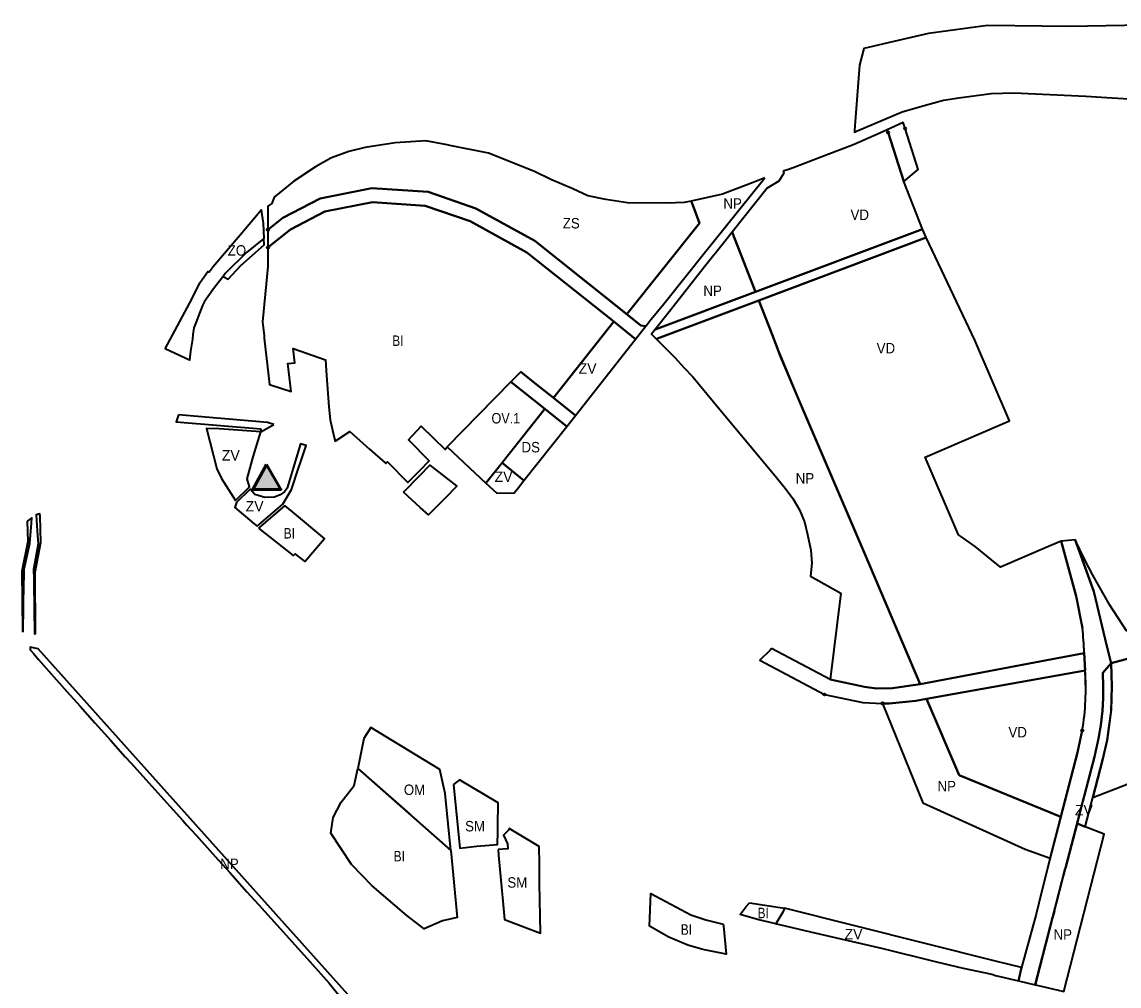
# Model space of a CAD drawing. Extents: x -650276 to -642489, y -1074311 to -1066658.
# Drawn here: x -650276 to -649019, y -1070272 to -1069167 of the extents above; entities that cross this region are included whole.
import ezdxf

# ---------------------------------------------------------------- set-up
doc = ezdxf.new("R2010")
doc.units = 0
doc.header["$LTSCALE"] = 4.8
doc.header["$PDMODE"] = 32
doc.header["$PDSIZE"] = 2.4
for name, color, linetype, lineweight in [('11', 7, 'Continuous', 35), ('12', 7, 'Continuous', 35), ('13', 7, 'Continuous', 35), ('15', 7, 'Continuous', 35), ('18', 7, 'Continuous', 35), ('2', 7, 'Continuous', 35), ('24', 7, 'Continuous', 35), ('35', 7, 'Continuous', 35), ('40', 7, 'Continuous', 35), ('41', 7, 'Continuous', 35), ('42', 7, 'Continuous', 35), ('48', 7, 'Continuous', 35), ('55', 7, 'Continuous', 53)]:
    doc.layers.add(name, color=color, linetype=linetype, lineweight=lineweight)
doc.layers.add('62', color=7, linetype='Continuous')

msp = doc.modelspace()

# ---------------------------------------------------------------- hatches: boundary and pattern name
at = {"layer": '55'}
msp.add_hatch(color=256, dxfattribs=at).paths.add_polyline_path([(-649995.793, -1069674.354), (-650011.744, -1069703), (-649979.36, -1069703)])

# ---------------------------------------------------------------- linework, layer by layer
at = {"layer": '11'}
msp.add_lwpolyline([(-649788.91, -1069654.4), (-649744.517, -1069695.746), (-649677.124, -1069610.681), (-649715.908, -1069579.804)], close=True, dxfattribs=at)
at = {"layer": '12'}
msp.add_lwpolyline([(-649891.21, -1070022.68), (-649832.007, -1070074.751), (-649784.87, -1070116.76), (-649791.31, -1070051.51), (-649797.45, -1070023.77), (-649876.31, -1069975.93), (-649884.59, -1069988.57)], close=True, dxfattribs=at)
at = {"layer": '13'}
msp.add_lwpolyline([(-648800.85, -1069841.52), (-649028.017, -1069902.109), (-649027.135, -1069928.902), (-649027.953, -1069955.702), (-649032.644, -1069990.371), (-649037.411, -1070011.659), (-649048.918, -1070055.852), (-648931.057, -1070010.171)], dxfattribs=at)
at = {"layer": '15'}
msp.add_line((-649057.868, -1069910.51), (-649058.82, -1069890.548), dxfattribs=at)
for points in [[(-649561.17, -1069515.83), (-649566.951, -1069515.099), (-649688.625, -1069418.156), (-649755.971, -1069381.179), (-649810.846, -1069362.154), (-649875.434, -1069357.751), (-649934.363, -1069369.537), (-649945.397, -1069375.277), (-649977.239, -1069391.714), (-649994.329, -1069405.451)], [(-649994.293, -1069425.949), (-649968.465, -1069405.189), (-649929.015, -1069384.784), (-649874.391, -1069373.859)], [(-649874.391, -1069373.859), (-649814.067, -1069377.972), (-649762.488, -1069395.854), (-649697.525, -1069431.522), (-649598.004, -1069510.814), (-649572.972, -1069530.758)], [(-649994.329, -1069405.451), (-649994.329, -1069405.451), (-649994.293, -1069425.949), (-649994.293, -1069425.949)], [(-649431.761, -1069486.57), (-649240.202, -1069414.528), (-649244.08, -1069404.753), (-649435.578, -1069476.772), (-649550.53, -1069519.68)], [(-649548.881, -1069530.963), (-649547.733, -1069530.185), (-649431.761, -1069486.57)], [(-649572.972, -1069530.758), (-649561.91, -1069516.78), (-649561.17, -1069515.83)], [(-649550.53, -1069519.68), (-649554.83, -1069525), (-649551.32, -1069528.49), (-649549.69, -1069530.14), (-649548.881, -1069530.963)], [(-650096.627, -1069617.746), (-650099.55, -1069625.53), (-650002.39, -1069633.65)], [(-649987.49, -1069628.6), (-649994.913, -1069626.246), (-650096.627, -1069617.746)], [(-650002.39, -1069633.65), (-650002.65, -1069637.14), (-649987.49, -1069628.6)], [(-649029.61, -1069835.47), (-649049.22, -1069801.23), (-649058.34, -1069783.72), (-649069.4, -1069760.67)], [(-649069.4, -1069760.67), (-649048, -1069820), (-649032.928, -1069882.782)], [(-649032.928, -1069882.782), (-649028.017, -1069902.109), (-648800.85, -1069841.52), (-648806.946, -1069821.79), (-648846.939, -1069832.584), (-648846.94, -1069832.584)], [(-648846.94, -1069832.584), (-648916.03, -1069847.12), (-649010.55, -1069865.09), (-649029.61, -1069835.47)], [(-649417.234, -1069885.193), (-649418.94, -1069887.36), (-649430.515, -1069898.514), (-649356.458, -1069937.945)], [(-649246.81, -1069926.27), (-649278.492, -1069930.573), (-649296.851, -1069931.092), (-649310.738, -1069929.342), (-649350.222, -1069920.873), (-649417.234, -1069885.193)], [(-649058.82, -1069890.548), (-649101.89, -1069898.73), (-649246.81, -1069926.27)], [(-649289.95, -1069948.146), (-649282.437, -1069948.342), (-649251.805, -1069945.276), (-649239.635, -1069943.094), (-649057.868, -1069910.51)], [(-649356.458, -1069937.945), (-649312.646, -1069947.342), (-649289.95, -1069948.146)]]:
    msp.add_lwpolyline(points, dxfattribs=at)
for points in [[(-650025.31, -1069446.49), (-649998.512, -1069422.926), (-649999.01, -1069415.628), (-650018.873, -1069431.749), (-650043.521, -1069455.69), (-650045.72, -1069459.1), (-650040.012, -1069461.999)], [(-649677.124, -1069610.681), (-649651.846, -1069630.82), (-649641.978, -1069618.226), (-649667.188, -1069598.14), (-649688.446, -1069581.203), (-649704.646, -1069568.296), (-649715.908, -1069579.804)]]:
    msp.add_lwpolyline(points, close=True, dxfattribs=at)
for p in [(-649994.329, -1069405.451), (-649994.293, -1069425.949), (-649356.458, -1069937.945), (-649289.95, -1069948.146)]:
    msp.add_point(p, dxfattribs=at)
at = {"layer": '18'}
for points in [[(-649781.53, -1070041.2), (-649774.45, -1070113.92), (-649754.82, -1070111.89), (-649731.12, -1070109.96), (-649730.96, -1070094.91), (-649730.89, -1070088.96), (-649730.6, -1070061.98), (-649774.73, -1070035.58)], [(-649730.57, -1070115.76), (-649730, -1070122.01), (-649726.22, -1070162.75), (-649725.49, -1070170.64), (-649723.17, -1070195.81), (-649682.04, -1070211.58), (-649683.12, -1070154.14), (-649682.98, -1070132.1), (-649683.57, -1070112.05), (-649717.72, -1070091.61), (-649718.71, -1070093.35), (-649724.36, -1070099.03), (-649719.69, -1070108.94), (-649719.24, -1070114.87)]]:
    msp.add_lwpolyline(points, close=True, dxfattribs=at)
at = {"layer": '2'}
for points in [[(-649715.908, -1069579.804), (-649704.646, -1069568.296), (-649688.446, -1069581.203), (-649667.188, -1069598.14), (-649598.004, -1069510.814), (-649697.525, -1069431.522), (-649762.488, -1069395.854), (-649814.067, -1069377.972), (-649874.391, -1069373.859), (-649929.015, -1069384.784), (-649968.465, -1069405.189), (-649994.293, -1069425.949), (-649994.53, -1069447.61), (-650000.59, -1069511.15), (-649998.81, -1069527.07), (-649998.5, -1069529.88), (-649992.59, -1069582.88), (-649967.81, -1069590.74), (-649971.38, -1069558.79), (-649963.43, -1069557.91), (-649965.26, -1069541.51), (-649928.48, -1069554.57), (-649927.3, -1069572.44)], [(-649927.3, -1069572.44), (-649924.62, -1069608.53), (-649923.17, -1069623.14), (-649918.35, -1069643.45), (-649917.38, -1069647.56), (-649900.64, -1069636.78), (-649877.82, -1069656.83), (-649859.96, -1069672.53), (-649859.17, -1069673.22), (-649857.49, -1069671.46), (-649833.94, -1069695.24), (-649833.94, -1069695.24), (-649819.98, -1069680.92), (-649809.47, -1069670.13), (-649833.38, -1069646.08), (-649818.71, -1069630.64), (-649791.3, -1069657.21), (-649788.91, -1069654.4), (-649715.908, -1069579.804)]]:
    msp.add_lwpolyline(points, dxfattribs=at)
for points in [[(-649838.99, -1069706.15), (-649820.64, -1069687.33), (-649808.96, -1069675.34), (-649777.94, -1069699.2), (-649792.13, -1069713.65), (-649807.66, -1069729.46), (-649810.41, -1069732.28), (-649819.9, -1069723.61)], [(-650004.59, -1069747.27), (-649974.86, -1069721.96), (-649966.52, -1069728.87), (-649929.38, -1069759.65), (-649951.56, -1069785.42), (-649963, -1069776.7), (-649965, -1069778.7)], [(-649922.3, -1070096.9), (-649919.55, -1070079.01), (-649910.34, -1070061.29), (-649895.45, -1070042.15), (-649891.21, -1070022.68), (-649784.87, -1070116.76), (-649777.29, -1070193.57), (-649794.37, -1070197.2), (-649815.33, -1070206.63), (-649835.28, -1070191.27), (-649874.94, -1070157.19), (-649898.55, -1070132.9)], [(-649557.21, -1070203.53), (-649555.44, -1070165.91), (-649532.57, -1070178.08), (-649509.72, -1070190.24), (-649492.67, -1070196.34), (-649472.6, -1070201.15), (-649472.43, -1070202.9), (-649469.176, -1070235.365), (-649496, -1070230), (-649513, -1070225), (-649535, -1070216)], [(-649442.63, -1070176.69), (-649402.29, -1070182.92), (-649404.2, -1070187.43), (-649412.2, -1070200.71), (-649433.3, -1070195.89), (-649453.27, -1070190.02), (-649446.19, -1070180.76)]]:
    msp.add_lwpolyline(points, close=True, dxfattribs=at)
at = {"layer": '24'}
for p, q in [((-649283.702, -1069294.132), (-649265.774, -1069350.068)), ((-649058.858, -1069889.759), (-649057.868, -1069910.51)), ((-649057.134, -1069932.873), (-649057.868, -1069910.51))]:
    msp.add_line(p, q, dxfattribs=at)
for points in [[(-648781.015, -1069167.44), (-649076.02, -1069172.683), (-649169.781, -1069171.432), (-649237.512, -1069180.731), (-649277.021, -1069189.913), (-649306.455, -1069196.754), (-649311.633, -1069197.958), (-649316.47, -1069216.91), (-649321.32, -1069281.47), (-649322.09, -1069291.73), (-649322.22, -1069293.54), (-649319.72, -1069292.47), (-649267.5, -1069270.41), (-649242.5, -1069263.3), (-649220.18, -1069257.03), (-649202.63, -1069254.4), (-649165.62, -1069249.43), (-649139.63, -1069248.73), (-649056.95, -1069252.55), (-649026.955, -1069254.366), (-649001.3, -1069255.92)], [(-649264.156, -1069289.589), (-649266.331, -1069282.804), (-649284.695, -1069291.033), (-649283.702, -1069294.132)], [(-649265.774, -1069350.068), (-649249.069, -1069336.66), (-649264.156, -1069289.589)], [(-649061.138, -1069979.243), (-649061.138, -1069979.243), (-649061.139, -1069979.254), (-649066.487, -1070004.267), (-649098.65, -1070127.795), (-649110.925, -1070177.113), (-649114.174, -1070189.816), (-649130.712, -1070250.935), (-649134.294, -1070266.095), (-649115.159, -1070270.568), (-649095.152, -1070193.731), (-649093.095, -1070186.132), (-649095.152, -1070193.731), (-649080.924, -1070137.409), (-649080.38, -1070136.996), (-649047.131, -1070009.304), (-649042.468, -1069988.477), (-649042.468, -1069988.477), (-649039.966, -1069973.035), (-649037.98, -1069956.626), (-649037.322, -1069942.129), (-649037.137, -1069928.996), (-649037.665, -1069912.977), (-649028.017, -1069902.109), (-649032.928, -1069882.782), (-649048, -1069820), (-649069.4, -1069760.67), (-649085.41, -1069762.44), (-649068, -1069825.147), (-649060.897, -1069861.994)]]:
    msp.add_lwpolyline(points, dxfattribs=at)
msp.add_lwpolyline([(-649701.211, -1069692.826), (-649651.773, -1069630.879), (-649677.124, -1069610.681), (-649726.033, -1069672.415)], close=True, dxfattribs=at)
for centre, radius, start, end in [((-649633.43, -1069918.001), 575.266, 2.81398, 5.58706), ((-649347.129, -1069931.193), 290, 350.46253, 4.08974), ((-649347.129, -1069931.193), 290, 359.66809, 4.08974)]:
    msp.add_arc(centre, radius, start, end, dxfattribs=at)
for p in [(-649283.702, -1069294.132), (-649264.156, -1069289.589)]:
    msp.add_point(p, dxfattribs=at)
at = {"layer": '35'}
msp.add_line((-649202.375, -1070030.469), (-649085.737, -1070078.201), dxfattribs=at)
for points in [[(-649283.702, -1069294.132), (-649284.695, -1069291.033), (-649300.133, -1069297.95), (-649321.69, -1069307.61)], [(-649244.08, -1069404.753), (-649265.774, -1069350.068), (-649283.702, -1069294.132)], [(-649321.69, -1069307.61), (-649324.3, -1069308.59), (-649359.48, -1069321.82), (-649389.4, -1069333.35), (-649396.52, -1069336.09), (-649403.92, -1069338.26)], [(-649403.92, -1069338.26), (-649403.03, -1069340.66), (-649408.81, -1069349.89), (-649422.19, -1069357.99), (-649462.25, -1069408.32), (-649435.578, -1069476.772), (-649244.08, -1069404.753)], [(-649060.897, -1069861.994), (-649068, -1069825.147), (-649085.41, -1069762.44), (-649085.41, -1069762.44), (-649099.75, -1069768.575), (-649154.76, -1069792.11), (-649184.05, -1069768.45), (-649200.64, -1069756.53), (-649202.99, -1069754.99), (-649241.11, -1069665.9), (-649155.082, -1069629.097), (-649144.57, -1069624.6), (-649184.1, -1069532.2), (-649240.202, -1069414.528), (-649431.761, -1069486.57), (-649416.52, -1069525.68), (-649409.355, -1069544.517), (-649388.438, -1069594.296), (-649379.32, -1069615.71), (-649364.44, -1069650.55), (-649312.03, -1069773.33)], [(-649312.03, -1069773.33), (-649246.81, -1069926.27), (-649101.89, -1069898.73), (-649058.82, -1069890.548)], [(-649057.868, -1069910.51), (-649239.635, -1069943.094), (-649202.375, -1070030.469)], [(-649085.737, -1070078.201), (-649066.487, -1070004.267), (-649061.139, -1069979.254), (-649061.138, -1069979.243)]]:
    msp.add_lwpolyline(points, dxfattribs=at)
for centre, radius, start, end in [((-649649.71, -1069919.176), 591.583, 2.77379, 5.54687), ((-649347.129, -1069931.193), 290, 350.46253, 4.08974)]:
    msp.add_arc(centre, radius, start, end, dxfattribs=at)
msp.add_point((-649061.138, -1069979.243), dxfattribs=at)
at = {"layer": '40'}
for points in [[(-649667.188, -1069598.14), (-649641.978, -1069618.226), (-649572.972, -1069530.758), (-649598.004, -1069510.814)], [(-650002.65, -1069637.14), (-650050.26, -1069633.65), (-650064.77, -1069633.06), (-650052.88, -1069679.49), (-650047.45, -1069690.69), (-650031.64, -1069715.9), (-650015.53, -1069700.21), (-650018.31, -1069690.89), (-650011.15, -1069665.82)], [(-649998, -1069712.26), (-650009.509, -1069708.678), (-650014.74, -1069702.9), (-650030.26, -1069717.96), (-650032.13, -1069723.75), (-650010.04, -1069742.58), (-650006.85, -1069745.3), (-649977.31, -1069720.05), (-649967.27, -1069703.29), (-649958.87, -1069677.59), (-649957.54, -1069673.5), (-649950.69, -1069652.54), (-649957.15, -1069650.76), (-649965.45, -1069678.6), (-649966.59, -1069682.44), (-649972.35, -1069701.78), (-649975.45, -1069705.65), (-649980.22, -1069709.07), (-649986.69, -1069712.03)], [(-649732.52, -1069706.92), (-649712.64, -1069707.43), (-649708.322, -1069702.293), (-649701.211, -1069692.826), (-649726.033, -1069672.415), (-649744.517, -1069695.746)], [(-649060.411, -1070060.306), (-649067.061, -1070085.844), (-649057.722, -1070089.665), (-649048.918, -1070055.852), (-649037.411, -1070011.659), (-649032.644, -1069990.371), (-649028.007, -1069957.455), (-649027.135, -1069928.902), (-649028.017, -1069902.109), (-649037.665, -1069912.977), (-649037.137, -1069928.996), (-649037.322, -1069942.129), (-649037.98, -1069956.626), (-649039.966, -1069973.035), (-649042.468, -1069988.477), (-649047.131, -1070009.304)], [(-649160.748, -1070243.413), (-649402.29, -1070182.92), (-649404.2, -1070187.43), (-649412.2, -1070200.71), (-649412.2, -1070200.71), (-649408.24, -1070201.62), (-649372.69, -1070209.74), (-649289.83, -1070229.16), (-649229.8, -1070243.94), (-649197.55, -1070251.65), (-649164.91, -1070258.55), (-649160.54, -1070259.96), (-649134.294, -1070266.095), (-649130.712, -1070250.935)]]:
    msp.add_lwpolyline(points, close=True, dxfattribs=at)
at = {"layer": '41'}
msp.add_lwpolyline([(-649934.363, -1069369.537), (-649875.434, -1069357.751), (-649810.846, -1069362.154), (-649755.971, -1069381.179), (-649688.625, -1069418.156), (-649582.972, -1069502.334), (-649499.761, -1069397.905), (-649507.61, -1069377.35), (-649509.42, -1069372.61), (-649517.17, -1069374.3), (-649537.32, -1069375.23), (-649582.25, -1069374.51), (-649607.18, -1069370.92), (-649627.76, -1069366.8), (-649645.03, -1069358.8), (-649670.23, -1069347.9), (-649688.73, -1069338.7), (-649690.59, -1069337.98), (-649741.5, -1069317.74), (-649785.8, -1069308.94), (-649789, -1069308.31), (-649813.3, -1069303.66), (-649848.62, -1069305.95), (-649882.93, -1069311.1), (-649901.58, -1069316.01), (-649921.54, -1069323.03), (-649922.11, -1069323.35), (-649939.81, -1069333.47), (-649964.53, -1069350.02), (-649987.12, -1069368.03), (-649989.67, -1069375.36), (-649994.38, -1069378.33), (-649994.35, -1069394.43), (-649994.34, -1069398.8), (-649994.329, -1069405.451), (-649977.239, -1069391.714), (-649945.397, -1069375.277)], close=True, dxfattribs=at)
at = {"layer": '42'}
msp.add_lwpolyline([(-650112.18, -1069542.11), (-650081.29, -1069484.35), (-650072.5, -1069466.44), (-650063.12, -1069453.54), (-650062.17, -1069454.05), (-650060.29, -1069451.7), (-650057.49, -1069448.18), (-650026.33, -1069411.47), (-650003.73, -1069384.71), (-650002.11, -1069382.8), (-650001.13, -1069388.13), (-649999.95, -1069397.98), (-649999.01, -1069415.628), (-650018.873, -1069431.749), (-650043.521, -1069455.69), (-650045.72, -1069459.1), (-650055.612, -1069471.639), (-650066.897, -1069487.541), (-650069.369, -1069492.132), (-650074.75, -1069506.133), (-650076.365, -1069510.333), (-650079.264, -1069517.874), (-650080.302, -1069525.418), (-650080.802, -1069530.768), (-650082.963, -1069544.736), (-650084.345, -1069554.773)], close=True, dxfattribs=at)
at = {"layer": '48'}
msp.add_line((-649499.761, -1069397.905), (-649582.972, -1069502.334), dxfattribs=at)
for points in [[(-649561.17, -1069515.83), (-649560.54, -1069515.02), (-649558.71, -1069512.62), (-649556.9, -1069510.24), (-649555.16, -1069508.07), (-649540.81, -1069490.25), (-649513.66, -1069456.53), (-649510.56, -1069452.67), (-649498.47, -1069437.65), (-649424.8, -1069346.14)], [(-649424.8, -1069346.14), (-649438.17, -1069351.27), (-649473.35, -1069364.76), (-649473.35, -1069364.76), (-649509.42, -1069372.61), (-649507.61, -1069377.35), (-649499.761, -1069397.905)], [(-649493.94, -1069448.14), (-649534.06, -1069499.33), (-649550.53, -1069519.68), (-649435.578, -1069476.772), (-649440.466, -1069464.229), (-649462.25, -1069408.32)], [(-649462.25, -1069408.32), (-649470.71, -1069418.95), (-649493.94, -1069448.14), (-649493.94, -1069448.14)], [(-649582.972, -1069502.334), (-649566.951, -1069515.099), (-649561.17, -1069515.83)], [(-649843.513, -1070347.685), (-650257.713, -1069885.547), (-650266.89, -1069883.7), (-650266.68, -1069886.78), (-650262.64, -1069891.57), (-650257.16, -1069898.07), (-650224.71, -1069934.41), (-650209.51, -1069951.43), (-650192.51, -1069970.47), (-650174.3, -1069990.86), (-650157.87, -1070009.26), (-650151.03, -1070016.84), (-650134.26, -1070035.45), (-650106.76, -1070065.96), (-650091.89, -1070082.46), (-650087.18, -1070087.68), (-650076.72, -1070099.29), (-650051.33, -1070127.45), (-650037.78, -1070142.48), (-650018.41, -1070163.97), (-650005.3, -1070178.51), (-649990.95, -1070194.43), (-649977.05, -1070209.85), (-649946.39, -1070243.87), (-649930.46, -1070261.54), (-649924.15, -1070268.55), (-649913.03, -1070282.44)], [(-649114.172, -1070266.777), (-649114.931, -1070270.621), (-649082.233, -1070278.265), (-649036.031, -1070097.854), (-649057.722, -1070089.665), (-649067.061, -1070085.844)], [(-649067.061, -1070085.844), (-649080.38, -1070136.996), (-649080.872, -1070137.369), (-649083.108, -1070146.053)], [(-649083.108, -1070146.053), (-649095.152, -1070193.731), (-649093.095, -1070186.132), (-649095.152, -1070193.731), (-649114.172, -1070266.777)]]:
    msp.add_lwpolyline(points, dxfattribs=at)
for points in [[(-649392.85, -1069713.53), (-649385.25, -1069726.48), (-649379.49, -1069740.04), (-649376.01, -1069754.58), (-649372.2, -1069772.58), (-649370.94, -1069787.45), (-649372.56, -1069802.33), (-649372.56, -1069802.33), (-649338, -1069822), (-649350.222, -1069920.873), (-649310.738, -1069929.342), (-649296.851, -1069931.092), (-649278.492, -1069930.573), (-649246.81, -1069926.27), (-649312.03, -1069773.33), (-649364.44, -1069650.55), (-649379.32, -1069615.71), (-649407.002, -1069550.701), (-649416.52, -1069525.68), (-649431.761, -1069486.57), (-649547.733, -1069530.185), (-649548.881, -1069530.963), (-649538.49, -1069541.54), (-649527.84, -1069552.16), (-649517.81, -1069563.27), (-649507.23, -1069573.85), (-649474.46, -1069613.59), (-649415.12, -1069685.26), (-649401.77, -1069701.47)], [(-650270.059, -1069739.232), (-650269.449, -1069762.714), (-650276.214, -1069796.532), (-650275.76, -1069865.474), (-650274.95, -1069865.62), (-650273.87, -1069809.74), (-650273.78, -1069805.2), (-650273.58, -1069794.48), (-650270.15, -1069778.65), (-650267.22, -1069765.1), (-650265.37, -1069741.61), (-650264.91, -1069735.69)], [(-650260.645, -1069868.536), (-650260.748, -1069867.327), (-650261.204, -1069797.969), (-650254.411, -1069764.006), (-650255.21, -1069733.253), (-650255.716, -1069731.162), (-650259.97, -1069732.29), (-650258.74, -1069750.62), (-650257.77, -1069765.2), (-650262.93, -1069794.84), (-650262.77, -1069805.54), (-650262.7, -1069809.89), (-650261.8, -1069868.33)], [(-649251.805, -1069945.276), (-649282.437, -1069948.342), (-649289.95, -1069948.146), (-649243.846, -1070062.071), (-649126.437, -1070115.217), (-649126.437, -1070115.217), (-649098.101, -1070125.688), (-649085.737, -1070078.201), (-649202.375, -1070030.469), (-649239.635, -1069943.094)]]:
    msp.add_lwpolyline(points, close=True, dxfattribs=at)
at = {"layer": '55'}
msp.add_lwpolyline([(-649995.793, -1069674.354), (-650011.744, -1069703), (-649979.36, -1069703)], close=True, dxfattribs=at)

# ---------------------------------------------------------------- texts
at = {"layer": '62'}
for s, width, p in [('NP', 0.95, (-649472.389, -1069381.42)), ('VD', 0.95, (-649326.761, -1069394.352)), ('ZS', 0.95, (-649656.482, -1069404.05)), ('ZO', 0.95, (-650040.423, -1069435.188)), ('NP', 0.95, (-649495.389, -1069481.42)), ('BI', 0.85, (-649851.88, -1069538.658)), ('VD', 0.95, (-649296.767, -1069547.204)), ('OV.1', 0.9, (-649738.147, -1069627.487)), ('DS', 0.95, (-649703.778, -1069660.629)), ('NP', 0.95, (-649389.556, -1069696.287)), ('BI', 0.85, (-649976.221, -1069759.292)), ('VD', 0.95, (-649145.767, -1069987.204)), ('OM', 0.95, (-649838.604, -1070053.132)), ('NP', 0.95, (-649227.076, -1070049.026)), ('SM', 0.95, (-649768.411, -1070094.846)), ('NP', 0.95, (-650048.985, -1070137.967)), ('BI', 0.85, (-649850.221, -1070129.292)), ('SM', 0.95, (-649719.964, -1070159.337)), ('BI', 0.85, (-649433.221, -1070194.292)), ('BI', 0.85, (-649521.221, -1070213.292)), ('NP', 0.95, (-649094.076, -1070219.026))]:
    msp.add_text(s, height=12, dxfattribs=dict(at, width=width)).set_placement(p)
for p in [(-649638.283, -1069570.48), (-650047.124, -1069669.988), (-649734.572, -1069694.498), (-650019.82, -1069728.32), (-649069.527, -1070076.528), (-649333.527, -1070218.528)]:
    msp.add_text('ZV', height=12, dxfattribs=at).set_placement(p)

doc.saveas('drawing.dxf')
